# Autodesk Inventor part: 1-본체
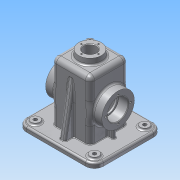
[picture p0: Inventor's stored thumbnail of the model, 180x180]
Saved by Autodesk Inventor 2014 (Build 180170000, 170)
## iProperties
Created: 2015-12
Part Number: 1-본체
Material: 알루미늄 6061
Document SubType Name: Modeling
Designer: Administrator
Density: 2.71 g/cm^3
Appearance: 알루미늄 - 평지
Mass: 861.363 g
Surface Area: 942.536 cm^2
Volume: 317.846 cm^3
Author: Administrator
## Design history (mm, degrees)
sketch "스케치1"
  geometry: L1 (-65, 57.5)-(65, 57.5); L2 (65, 57.5)-(65, -57.5); L3 (65, -57.5)-(-65, -57.5); L4 (-65, -57.5)-(-65, 57.5); L5 (-65, 57.5)-(65, -57.5); L6 (65, 57.5)-(-65, -57.5); 1 further point
  constraints: 12 end point, 2 midpoint, 2 parallel, 1 horizontal, 1 perpendicular
  dimensions: "d0" = 130 distance of L2.end L3.end; "d1" = 115 distance of L1.end L2.end
extrude "돌출1" new body sketch "스케치1" distance "d2" = 8; taper "d3" = 0 deg
sketch "스케치2"
  geometry: L1 (-60, 52.5)-(60, 52.5); L2 (60, 52.5)-(60, -52.5); L3 (60, -52.5)-(-60, -52.5); L4 (-60, -52.5)-(-60, 52.5); L5 (-60, 52.5)-(60, -52.5); L6 (60, 52.5)-(-60, -52.5); 1 further point
  constraints: 12 end point, 2 midpoint, 2 parallel, 1 horizontal, 1 perpendicular
  dimensions: "d4" = 120 distance of L2.end L3.end; "d5" = 105 distance of L1.end L2.end
extrude "돌출2" join sketch "스케치2" distance "d6" = 2; taper "d7" = 0 deg
sketch "스케치3"
  geometry: C1 r 7.5 at (-50, 42.5); C2 r 7.5 at (50, 42.5); 1 further point
  constraints: 2 centre point
  dimensions: "d8" = 15 diameter of C1; "d9" = 15 diameter of C2; "d12" = 42.5 vertical distance of C2.centre point (0, 0); "d13" = 50 horizontal distance of point (0, 0) C2.centre; "d14" = 50 horizontal distance of point (0, 0) C1.centre; "d15" = 42.5 vertical distance of point (0, 0) C1.centre
extrude "돌출3" join sketch "스케치3" distance "d16" = 3; taper "d17" = 0 deg
sketch "스케치4"
  geometry: C1 r 7.5 at (0, 0) reference; C2 r 3 at (0, 0); 1 further point
  constraints: 1 centre point, 1 coincident
  dimensions: "d18" = 6 diameter of C2
extrude "돌출4" cut sketch "스케치4" distance "d19" = 20; taper "d20" = 0 deg
sketch "스케치5"
  geometry: C1 r 7.5 at (0, 0) reference; C2 r 3 at (0, 0); 1 further point
  constraints: 1 centre point, 1 coincident
  dimensions: "d21" = 6 diameter of C2
extrude "돌출5" cut sketch "스케치5" distance "d22" = 20; taper "d23" = 0 deg
sketch "스케치6"
  geometry: L1 (-32.5, 32.5)-(32.5, 32.5); L2 (32.5, 32.5)-(32.5, -32.5); L3 (32.5, -32.5)-(-32.5, -32.5); L4 (-32.5, -32.5)-(-32.5, 32.5); L5 (-32.5, 32.5)-(32.5, -32.5); L6 (32.5, 32.5)-(-32.5, -32.5); 1 further point
  constraints: 12 end point, 2 midpoint, 2 parallel, 1 horizontal, 1 perpendicular
  dimensions: "d24" = 65 distance of L2.end L3.end; "d25" = 65 distance of L1.end L2.end
extrude "돌출6" join sketch "스케치6" distance "d26" = 100; taper "d27" = 0 deg
sketch "스케치7"
  geometry: C1 r 20 at (0, 0); 1 further point
  constraints: 1 centre point, 1 coincident
  dimensions: "d28" = 40 diameter of C1
extrude "돌출7" join sketch "스케치7" distance "d29" = 10; taper "d30" = -5 deg
sketch "스케치8"
  geometry: L1 (-10, -20)-(-10, 85) reference; L2 (-8, 90)-(0, 90) reference; C1 r 27.5 at (45, 32.5); 1 further point
  constraints: 1 centre point
  dimensions: "d31" = 55 diameter of C1; "d32" = 55 distance from line of C1.centre L1; "d34" = 57.5 distance from line of C1.centre L2
extrude "돌출8" join sketch "스케치8" distance "d35" = 15; taper "d36" = 0 deg
sketch "스케치9"
  geometry: L1 (8, 90)-(0, 90) reference; L2 (10, 85)-(10, -20) reference; C1 r 27.5 at (-45, 32.5); 1 further point
  constraints: 1 centre point
  dimensions: "d37" = 55 diameter of C1; "d38" = 57.5 distance from line of C1.centre L1; "d39" = 55 distance from line of L2 C1.centre
extrude "돌출9" join sketch "스케치9" distance "d40" = 15; taper "d41" = 0 deg
fillet "모깎기5" dims "d99" = 3
sketch "스케치10"
  geometry: L1 (57.5, 8)-(57.5, 0) reference; L2 (57.5, 0)-(52.5, 0) reference; L3 (52.5, 0)-(52.5, -2) reference; L4 (52.5, -2)-(-52.5, -2) reference; L5 (-52.5, -2)-(-52.5, 0) reference; L6 (-52.5, 0)-(-57.5, 0) reference; L7 (-57.5, 0)-(-57.5, 8) reference; L8 (-57.5, 8)-(-32.5, 8) reference; L9 (-32.5, 8)-(-32.5, 108) reference; L10 (-32.5, 108)-(-20, 108) reference; L11 (-20, 108)-(-19.125, 118) reference; L12 (-19.125, 118)-(19.125, 118) reference; L13 (19.125, 118)-(20, 108) reference; L14 (20, 108)-(32.5, 108) reference; L15 (32.5, 108)-(32.5, 8) reference; L16 (32.5, 8)-(57.5, 8) reference; L17 (-47.5, 8)-(-32.5, 93.069); 1 further point
  constraints: 2 end point, 2 point on line
  dimensions: "d42" = 10 distance from line of L17.start L7; "d43" = 100 deg angle of L17 L8
extrude "돌출10" join sketch "스케치10" stored distance "d44" = 10; taper "d45" = 0 deg
sketch "스케치11"
  geometry: L1 (-27.5, 27.5)-(27.5, 27.5); L2 (27.5, 27.5)-(27.5, -27.5); L3 (27.5, -27.5)-(-27.5, -27.5); L4 (-27.5, -27.5)-(-27.5, 27.5); L5 (-27.5, 27.5)-(27.5, -27.5); L6 (27.5, 27.5)-(-27.5, -27.5); 1 further point
  constraints: 12 end point, 2 midpoint, 2 parallel, 1 horizontal, 1 perpendicular
  dimensions: "d46" = 55 distance of L2.end L3.end; "d47" = 55 distance of L1.end L2.end
extrude "돌출11" cut sketch "스케치11" distance "d48" = 110; taper "d49" = 0 deg
sketch "스케치12"
  geometry: L1 (-42.5, 25.5)-(-42.5, 8); L2 (-60, -2)-(-60, 0) reference; L3 (-60, 0)-(-65, 0) reference; L4 (-65, 0)-(-65, 8) reference; L5 (-65, 8)-(-32.5, 8) reference; L6 (-32.5, 8)-(-32.5, 22.5) reference; L7 (-35.5, 25.5)-(-47.5, 25.5) reference; L8 (-47.5, 25.5)-(-47.5, 80.5) reference; L9 (-47.5, 80.5)-(-35.5, 80.5) reference; L10 (-32.5, 108)-(-27.5, 108) reference; L11 (-20, 108)-(-19.125, 118) reference; L12 (-19.125, 118)-(19.125, 118) reference; L13 (19.125, 118)-(20, 108) reference; L14 (27.5, 108)-(32.5, 108) reference; L15 (35.5, 80.5)-(47.5, 80.5) reference; L16 (47.5, 80.5)-(47.5, 25.5) reference; L17 (47.5, 25.5)-(35.5, 25.5) reference; L18 (32.5, 22.5)-(32.5, 8) reference; L19 (32.5, 8)-(65, 8) reference; L20 (65, 8)-(65, 0) reference; L21 (65, 0)-(60, 0) reference; L22 (60, 0)-(60, -2) reference; L23 (60, -2)-(27.5, -2) reference; L24 (27.5, -2)-(27.5, 108) reference; L25 (-27.5, 108)-(-27.5, -2) reference; L26 (-27.5, -2)-(-60, -2) reference; L27 (-32.5, 83.5)-(-32.5, 108) reference; L28 (32.5, 108)-(32.5, 83.5) reference; L29 (20, 108)-(-20, 108) reference; A1 r 3 centre (-35.5, 22.5) between (-32.5, 22.5) and (-35.5, 25.5) reference; A2 r 3 centre (35.5, 83.5) between (32.5, 83.5) and (35.5, 80.5) reference; 5 further points
  constraints: 2 end point, 2 point on line, 1 vertical, 2 other
  dimensions: "d51" = 15 distance between parallel lines of L25 L1
extrude "돌출12" join sketch "스케치12" stored distance "d52" = 6; taper "d53" = 0 deg
sketch "스케치13"
  geometry: C1 r 19.125 at (0, 0) reference; C2 r 10.5 at (0, 0)
  constraints: 1 centre point, 1 coincident
  dimensions: "d54" = 21 diameter of C2
extrude "돌출13" cut sketch "스케치13" distance "d55" = 20; taper "d56" = 0 deg
sketch "스케치14"
  geometry: C1 r 27.5 at (0, 0) reference; C2 r 17.5 at (0, 0); 1 further point
  constraints: 1 centre point, 1 coincident
  dimensions: "d57" = 35 diameter of C2
extrude "돌출14" cut sketch "스케치14" distance "d58" = 17; taper "d59" = 0 deg
sketch "스케치15"
  geometry: C1 r 27.5 at (0, 0) reference; C2 r 17.5 at (0, 0); 1 further point
  constraints: 1 centre point, 1 coincident
  dimensions: "d60" = 35 diameter of C2
extrude "돌출15" cut sketch "스케치15" distance "d61" = 17; taper "d62" = 0 deg
sketch "스케치16"
  geometry: C1 r 17.5 at (0, 0) reference; C2 r 15 at (0, 0); 1 further point
  constraints: 1 centre point, 1 coincident
  dimensions: "d63" = 30 diameter of C2
extrude "돌출16" cut sketch "스케치16" distance "d64" = 3; taper "d65" = 0 deg
sketch "스케치17"
  geometry: C1 r 17.5 at (0, 0) reference; C2 r 15 at (0, 0); 1 further point
  constraints: 1 centre point, 1 coincident
  dimensions: "d66" = 30 diameter of C2
extrude "돌출17" cut sketch "스케치17" distance "d67" = 3; taper "d68" = 0 deg
sketch "스케치18"
  geometry: C1 r 10.5 at (0, 0) reference; 1 further point
  constraints: 1 vertical alignment
  dimensions: "d69" = 14.5 distance of point (0, 14.5) C1.centre
hole "구멍1" sketch "스케치18" at (0, 14.5) diameter "d70" = 2.459; stored, may be unused: countersink angle "d74" = 90 deg, drill point angle "d76" = 118 deg; dims "d71" = 7, "d72" = 4, "d73" = 2, "d75" = 9
sketch "스케치19"
  geometry: C1 r 17.5 at (0, 0) reference; 2 further points
  constraints: 1 horizontal alignment
  dimensions: "d80" = 21 distance of point (21, 0) C1.centre
hole "구멍2" sketch "스케치19" at (21, 0) diameter "d81" = 3.459; stored, may be unused: countersink angle "d85" = 90 deg, drill point angle "d87" = 118 deg; dims "d82" = 8, "d83" = 4, "d84" = 2, "d86" = 10
sketch "스케치20"
  geometry: L1 (-100, 65)-(0, 65) reference; L2 (10, 51.625)-(10, 13.375) reference; 2 further points
  constraints: 1 other
  dimensions: "d91" = 32.5 distance from line of point (-16, 32.5) L1; "d92" = 26 distance from line of L2 point (-16, 32.5)
feature "엠보싱1" sketch "스케치20" dims "d15" = 42.5, "d93" = 0.5, "d94" = 0
sketch "스케치21"
  geometry: L1 (27.5, 27.5)-(27.5, -27.5) reference; L2 (27.5, -27.5)-(-27.5, -27.5) reference; L3 (-27.5, -27.5)-(-27.5, 27.5) reference; L4 (-27.5, 27.5)-(27.5, 27.5) reference; 1 further point
extrude "돌출18" join sketch "스케치21" distance "d117" = 5; taper "d118" = 0 deg
sketch "스케치22"
  geometry: C1 r 10.5 at (0, 0) reference
extrude "돌출19" cut sketch "스케치22" distance "d119" = 5; taper "d120" = 0 deg
fillet "모깎기20" dims "d121" = 8
fillet "모깎기21" dims "d122" = 8
fillet "모깎기22" dims "d123" = 3
fillet "모깎기23" dims "d124" = 3
fillet "모깎기24" dims "d125" = 3
fillet "모깎기25" dims "d126" = 1
fillet "모깎기26" dims "d127" = 15
fillet "모깎기27" dims "d128" = 10
fillet "모깎기28" dims "d129" = 3
fillet "모깎기29" dims "d130" = 3
fillet "모깎기30" dims "d131" = 3
chamfer "모따기2" distance "d132" = 1; stored, may be unused: second distance "d133" = 2, angle "d134" = 45 deg
fillet "모깎기31" dims "d135" = 3
fillet "모깎기32" dims "d136" = 0.3
node "솔리드1"
mirror "대칭1"
mirror "대칭2"
mirror "대칭3"
pattern_circular "원형 패턴1" dims angle "d78" = 360 deg
pattern_circular "원형 패턴2" dims angle "d89" = 360 deg
mirror "대칭4"
node "절단 모서리 투영1"
node "절단 모서리 투영2"
